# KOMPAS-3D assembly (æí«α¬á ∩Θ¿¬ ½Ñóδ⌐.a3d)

Referenced files in D:\МОДЕЛЬ ТАНКА Т90\ДЕТАЛИ\БАШНЯ\башня сварная\: ящик левый.m3d
Referenced files in D:\МОДЕЛЬ ТАНКА Т90\ДЕТАЛИ\ОБЩИЕ ДЕТАЛИ\: шарниры ящиков.m3d, замки ящиков.m3d
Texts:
  Сборка ящик левый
